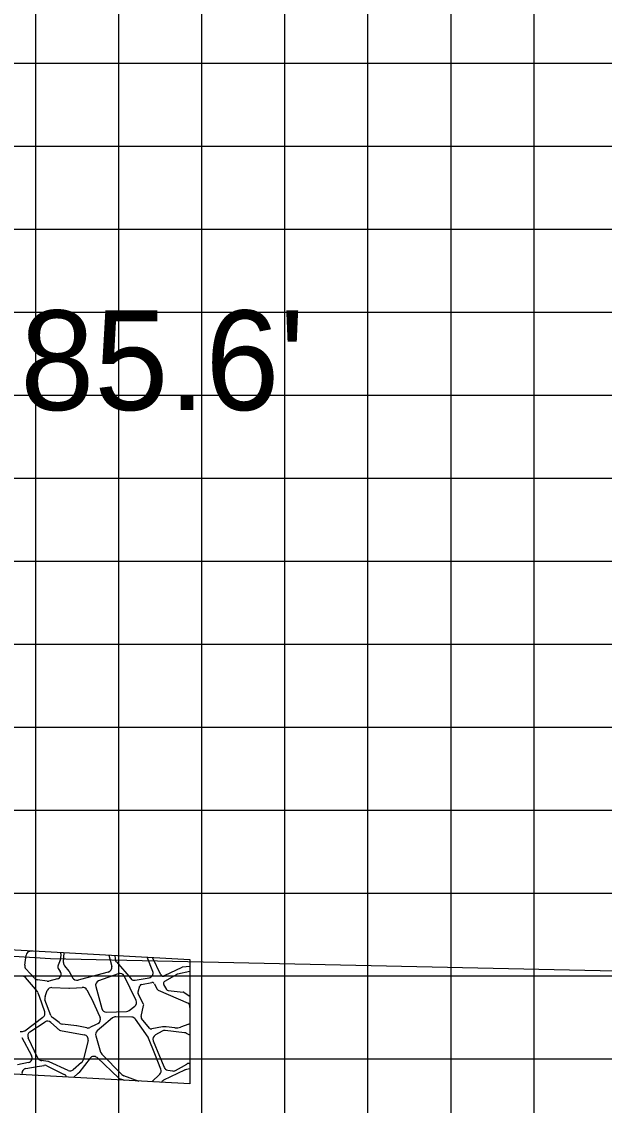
# Model space of a CAD drawing. Extents: x 1807832 to 1808175, y 442591 to 442811.
# Drawn here: x 1808081.61 to 1808088.63, y 442717.11 to 442730.17 of the extents above; entities that cross this region are included whole.
import ezdxf

# ---------------------------------------------------------------- set-up
doc = ezdxf.new("R2010")
doc.units = 0
for name, color, linetype in [('D_Roadway_SlopeLines', 7, 'Continuous'), ('D_Text_Standard', 7, 'Continuous'), ('MAJOR', 7, 'Continuous'), ('MINOR', 7, 'Continuous'), ('S_Roadway_Centerline', 7, 'Continuous')]:
    doc.layers.add(name, color=color, linetype=linetype)

msp = doc.modelspace()

# ---------------------------------------------------------------- linework, layer by layer
at = {"layer": 'D_Roadway_SlopeLines'}
for p, q in [((1808081.711, 442718.963), (1808081.742, 442718.968)), ((1808081.649, 442718.797), (1808081.665, 442718.914)), ((1808082.076, 442718.856), (1808082.053, 442718.796)), ((1808082.083, 442718.934), (1808082.08, 442718.873)), ((1808082.118, 442718.827), (1808082.126, 442718.947)), ((1808082.664, 442718.917), (1808082.697, 442718.78)), ((1808082.734, 442718.914), (1808082.74, 442718.866)), ((1808082.753, 442718.835), (1808082.926, 442718.633)), ((1808083.192, 442718.721), (1808083.125, 442718.892)), ((1808083.291, 442718.678), (1808083.187, 442718.888)), ((1808081.769, 442718.637), (1808081.664, 442718.751)), ((1808082.059, 442718.742), (1808082.076, 442718.719)), ((1808082.183, 442718.724), (1808082.131, 442718.786)), ((1808082.227, 442718.644), (1808082.189, 442718.714)), ((1808082.656, 442718.712), (1808082.322, 442718.623)), ((1808082.777, 442718.693), (1808082.539, 442718.607)), ((1808083.541, 442718.768), (1808083.329, 442718.665)), ((1808083.638, 442718.721), (1808083.491, 442718.689)), ((1808083.638, 442718.779), (1808083.551, 442718.771)), ((1808081.802, 442718.48), (1808081.657, 442718.645)), ((1808081.919, 442718.602), (1808081.803, 442718.619)), ((1808082.044, 442718.631), (1808081.941, 442718.604)), ((1808082.322, 442718.623), (1808082.292, 442718.615)), ((1808082.992, 442718.371), (1808082.847, 442718.665)), ((1808082.979, 442718.614), (1808083.149, 442718.644)), ((1808083.058, 442718.564), (1808083.18, 442718.588)), ((1808083.211, 442718.572), (1808083.242, 442718.509)), ((1808083.323, 442718.561), (1808083.357, 442718.503)), ((1808083.482, 442718.685), (1808083.334, 442718.6)), ((1808081.827, 442718.419), (1808081.813, 442718.46)), ((1808081.894, 442718.418), (1808081.921, 442718.489)), ((1808081.977, 442718.526), (1808082.181, 442718.517)), ((1808082.187, 442718.517), (1808082.272, 442718.523)), ((1808082.272, 442718.523), (1808082.343, 442718.528)), ((1808082.398, 442718.497), (1808082.477, 442718.344)), ((1808082.504, 442718.539), (1808082.577, 442718.272)), ((1808083.014, 442718.473), (1808083.036, 442718.545)), ((1808083.079, 442718.327), (1808083.015, 442718.452)), ((1808083.256, 442718.495), (1808083.618, 442718.338)), ((1808083.378, 442718.489), (1808083.558, 442718.47)), ((1808083.57, 442718.466), (1808083.638, 442718.423)), ((1808081.89, 442718.232), (1808081.827, 442718.419)), ((1808081.964, 442718.188), (1808081.893, 442718.377)), ((1808082.478, 442718.341), (1808082.531, 442718.224)), ((1808082.909, 442718.251), (1808082.975, 442718.301)), ((1808083.052, 442718.177), (1808083.082, 442718.308)), ((1808083.635, 442718.313), (1808083.639, 442718.25)), ((1808081.649, 442718.005), (1808081.869, 442718.168)), ((1808082.531, 442718.224), (1808082.558, 442718.166)), ((1808082.634, 442718.23), (1808082.876, 442718.239)), ((1808082.938, 442718.169), (1808082.745, 442718.173)), ((1808081.711, 442717.991), (1808081.894, 442718.112)), ((1808081.964, 442718.106), (1808082.033, 442718.043)), ((1808082.063, 442718.104), (1808081.984, 442718.163)), ((1808082.033, 442718.043), (1808082.054, 442718.023)), ((1808082.077, 442718.094), (1808082.063, 442718.104)), ((1808082.273, 442718.064), (1808082.104, 442718.084)), ((1808082.397, 442718.039), (1808082.277, 442718.063)), ((1808082.509, 442718.08), (1808082.433, 442718.043)), ((1808082.531, 442718.09), (1808082.509, 442718.08)), ((1808082.574, 442718.047), (1808082.522, 442718.003)), ((1808082.707, 442718.159), (1808082.574, 442718.047)), ((1808083.136, 442717.926), (1808082.984, 442718.145)), ((1808083.153, 442718.038), (1808083.058, 442718.152)), ((1808083.31, 442718.052), (1808083.18, 442718.028)), ((1808083.458, 442718.039), (1808083.354, 442718.053)), ((1808083.628, 442718.086), (1808083.527, 442718.048)), ((1808081.613, 442717.922), (1808081.731, 442717.707)), ((1808081.808, 442717.676), (1808081.691, 442717.919)), ((1808082.082, 442718.009), (1808082.367, 442717.956)), ((1808082.504, 442717.942), (1808082.564, 442717.747)), ((1808083.217, 442717.727), (1808083.142, 442717.915)), ((1808083.305, 442718.001), (1808083.223, 442717.954)), ((1808083.576, 442717.981), (1808083.34, 442718.008)), ((1808083.639, 442717.95), (1808083.598, 442717.974)), ((1808082.412, 442717.886), (1808082.353, 442717.651)), ((1808083.198, 442717.883), (1808083.274, 442717.698)), ((1808081.926, 442717.636), (1808081.853, 442717.645)), ((1808082.437, 442717.675), (1808082.302, 442717.5)), ((1808082.784, 442717.434), (1808082.521, 442717.681)), ((1808082.578, 442717.724), (1808082.82, 442717.477)), ((1808083.29, 442717.544), (1808083.217, 442717.727)), ((1808083.274, 442717.698), (1808083.33, 442717.565)), ((1808081.694, 442717.624), (1808081.562, 442717.595)), ((1808081.663, 442717.55), (1808081.799, 442717.574)), ((1808081.799, 442717.574), (1808081.882, 442717.588)), ((1808081.917, 442717.583), (1808082.125, 442717.479)), ((1808082.173, 442717.528), (1808081.942, 442717.631)), ((1808082.334, 442717.621), (1808082.232, 442717.536)), ((1808083.574, 442717.53), (1808083.321, 442717.408)), ((1808083.373, 442717.53), (1808083.429, 442717.521)), ((1808083.466, 442717.527), (1808083.538, 442717.567)), ((1808083.538, 442717.567), (1808083.602, 442717.603)), ((1808083.598, 442717.537), (1808083.586, 442717.534)), ((1808083.64, 442717.546), (1808083.598, 442717.537)), ((1808083.63, 442717.611), (1808083.64, 442717.611)), ((1808081.618, 442717.475), (1808081.617, 442717.481)), ((1808082.294, 442717.492), (1808082.236, 442717.441)), ((1808082.855, 442717.407), (1808082.807, 442717.421)), ((1808082.841, 442717.464), (1808083.024, 442717.398)), ((1808083.179, 442717.389), (1808083.276, 442717.482))]:
    msp.add_line(p, q, dxfattribs=at)
msp.add_lwpolyline([(1808072.387, 442719.485), (1808083.638, 442718.864), (1808083.64, 442717.364), (1808072.389, 442717.985)], dxfattribs=at)
for centre, radius, start, end in [((1808081.722, 442718.907), 0.057, 100.5431, 172.2645), ((1808082.026, 442718.937), 0.057, 356.9084, 13.0529), ((1808082.023, 442718.876), 0.057, 338.7176, 356.9084), ((1808082.174, 442718.823), 0.057, 176.0026, 219.8938), ((1808082.796, 442718.872), 0.057, 186.4857, 220.501), ((1808081.706, 442718.789), 0.057, 172.2645, 222.5497), ((1808082.03, 442718.686), 0.057, 284.7091, 35.8237), ((1808082.106, 442718.775), 0.057, 158.7176, 215.8237), ((1808082.139, 442718.687), 0.057, 28.3056, 39.8938), ((1808082.642, 442718.767), 0.057, 284.7802, 13.4807), ((1808082.796, 442718.64), 0.057, 26.1599, 109.9553), ((1808083.139, 442718.7), 0.057, 280.1303, 21.4008), ((1808083.497, 442718.661), 0.0285, 102.2974, 119.8331), ((1808083.553, 442718.743), 0.0285, 94.8962, 116.1178), ((1808081.614, 442718.608), 0.057, 41.217, 102.183), ((1808081.811, 442718.675), 0.057, 222.5497, 261.9581), ((1808081.927, 442718.659), 0.057, 261.9581, 284.7091), ((1808082.277, 442718.671), 0.057, 208.3056, 284.7802), ((1808082.559, 442718.554), 0.057, 109.9553, 195.3566), ((1808082.969, 442718.67), 0.057, 220.501, 280.1303), ((1808083.064, 442718.536), 0.0285, 101.058, 162.2694), ((1808083.185, 442718.56), 0.0285, 25.9546, 101.058), ((1808083.316, 442718.69), 0.0285, 206.1178, 296.1178), ((1808083.348, 442718.575), 0.0285, 119.8331, 209.8331), ((1808081.759, 442718.442), 0.057, 18.5232, 41.217), ((1808081.974, 442718.469), 0.057, 87.4857, 158.7176), ((1808082.183, 442718.574), 0.057, 267.4857, 274.1739), ((1808082.347, 442718.471), 0.057, 26.9943, 94.1739), ((1808083.041, 442718.465), 0.0285, 162.2694, 207.2096), ((1808083.267, 442718.521), 0.0285, 205.9546, 246.5135), ((1808083.381, 442718.517), 0.0285, 209.8331, 264.0067), ((1808083.555, 442718.442), 0.0285, 57.951, 84.0067), ((1808081.947, 442718.398), 0.057, 158.7176, 190.1049), ((1808081.947, 442718.398), 0.057, 190.1049, 200.6443), ((1808082.426, 442718.318), 0.057, 24.4293, 26.9943), ((1808082.94, 442718.346), 0.057, 307.0163, 26.1599), ((1808083.054, 442718.314), 0.0285, 347.284, 27.2096), ((1808083.607, 442718.312), 0.0285, 3.3152, 66.5135), ((1808081.836, 442718.213), 0.057, 306.4923, 18.5232), ((1808082.018, 442718.209), 0.057, 200.6443, 233.6574), ((1808082.583, 442718.248), 0.057, 204.4293, 204.8634), ((1808082.506, 442718.142), 0.057, 295.4762, 24.8634), ((1808082.632, 442718.287), 0.057, 195.3566, 272.2807), ((1808082.744, 442718.116), 0.057, 88.9271, 130.1676), ((1808082.874, 442718.296), 0.057, 272.2807, 307.0163), ((1808082.937, 442718.112), 0.057, 34.8172, 88.9271), ((1808083.08, 442718.17), 0.0285, 167.284, 219.663), ((1808081.925, 442718.064), 0.057, 47.5778, 123.3497), ((1808082.111, 442718.14), 0.057, 233.6574, 263.177), ((1808082.266, 442718.007), 0.057, 78.7783, 83.177), ((1808082.408, 442718.095), 0.057, 258.7783, 295.4762), ((1808083.175, 442718.056), 0.0285, 219.663, 280.2876), ((1808083.335, 442717.912), 0.142, 82.6568, 100.2876), ((1808083.476, 442718.181), 0.142, 262.6568, 290.8447), ((1808083.618, 442718.113), 0.0285, 290.8447, 316.9574), ((1808081.615, 442718.051), 0.057, 249.1225, 306.4923), ((1808081.742, 442717.944), 0.057, 123.3497, 205.829), ((1808082.093, 442718.065), 0.057, 227.5778, 259.4686), ((1808082.357, 442717.9), 0.057, 345.9306, 79.4686), ((1808082.559, 442717.959), 0.057, 130.1676, 197.0964), ((1808083.089, 442717.894), 0.057, 21.7644, 34.8172), ((1808083.251, 442717.905), 0.057, 119.5267, 202.4169), ((1808083.333, 442717.951), 0.057, 83.4488, 119.5267), ((1808083.569, 442717.924), 0.057, 60.2987, 83.4488), ((1808081.682, 442717.679), 0.057, 282.4077, 28.9607), ((1808081.86, 442717.701), 0.057, 205.829, 246.202), ((1808081.86, 442717.701), 0.057, 246.202, 262.9632), ((1808082.298, 442717.664), 0.057, 309.5607, 345.9306), ((1808082.482, 442717.64), 0.057, 46.7902, 142.2299), ((1808082.619, 442717.764), 0.057, 197.0964, 224.4594), ((1808081.673, 442717.494), 0.057, 99.7424, 192.9944), ((1808081.891, 442717.532), 0.057, 63.612, 99.7424), ((1808081.919, 442717.579), 0.057, 65.9598, 82.9632), ((1808082.196, 442717.58), 0.057, 245.9598, 309.5607), ((1808083.237, 442717.523), 0.057, 313.6027, 21.7644), ((1808083.382, 442717.586), 0.057, 202.4169, 260.3816), ((1808083.438, 442717.577), 0.057, 260.3816, 299.3075), ((1808083.598, 442717.479), 0.057, 102.183, 115.7475), ((1808083.63, 442717.554), 0.057, 90.0882, 119.3075), ((1808082.1, 442717.428), 0.057, 17.8362, 63.612), ((1808082.257, 442717.535), 0.057, 311.0007, 322.2299), ((1808082.823, 442717.476), 0.057, 226.7902, 253.6775), ((1808082.861, 442717.517), 0.057, 224.4594, 250.0477), ((1808083.346, 442717.357), 0.057, 115.7475, 153.3813)]:
    msp.add_arc(centre, radius, start, end, dxfattribs=at)
at = {"layer": 'MAJOR'}
for p, q in [((1808087.785, 442708.665), (1808087.785, 442738.665)), ((1807857.785, 442728.665), (1808137.785, 442728.665)), ((1807857.785, 442723.665), (1808137.785, 442723.665)), ((1807857.785, 442718.665), (1808137.785, 442718.665))]:
    msp.add_line(p, q, dxfattribs=at)
at = {"layer": 'MINOR'}
for p, q in [((1808081.785, 442708.665), (1808081.785, 442738.665)), ((1808082.785, 442708.665), (1808082.785, 442738.665)), ((1808083.785, 442708.665), (1808083.785, 442738.665)), ((1808084.785, 442708.665), (1808084.785, 442738.665)), ((1808085.785, 442708.665), (1808085.785, 442738.665)), ((1808086.785, 442708.665), (1808086.785, 442738.665)), ((1807857.785, 442729.665), (1808137.785, 442729.665)), ((1807857.785, 442727.665), (1808137.785, 442727.665)), ((1807857.785, 442726.665), (1808137.785, 442726.665)), ((1807857.785, 442725.665), (1808137.785, 442725.665)), ((1807857.785, 442724.665), (1808137.785, 442724.665)), ((1807857.785, 442722.665), (1808137.785, 442722.665)), ((1807857.785, 442721.665), (1808137.785, 442721.665)), ((1807857.785, 442720.665), (1808137.785, 442720.665)), ((1807857.785, 442719.665), (1808137.785, 442719.665)), ((1807857.785, 442717.665), (1808137.785, 442717.665))]:
    msp.add_line(p, q, dxfattribs=at)
at = {"layer": 'S_Roadway_Centerline'}
msp.add_lwpolyline([(1808048.448, 442720.043), (1808059.943, 442719.833), (1808068.47, 442719.682), (1808070.712, 442719.592), (1808081.958, 442718.876), (1808090.973, 442718.68), (1808097.443, 442718.589), (1808105.538, 442718.533), (1808112.951, 442718.382), (1808121.669, 442717.984), (1808133.631, 442717.501), (1808137.785, 442717.407)], dxfattribs=at)

# ---------------------------------------------------------------- texts
at = {"layer": 'D_Text_Standard'}
msp.add_text("85.6'", height=1.2, dxfattribs=at).set_placement((1808081.595, 442725.485))

doc.saveas('drawing.dxf')
